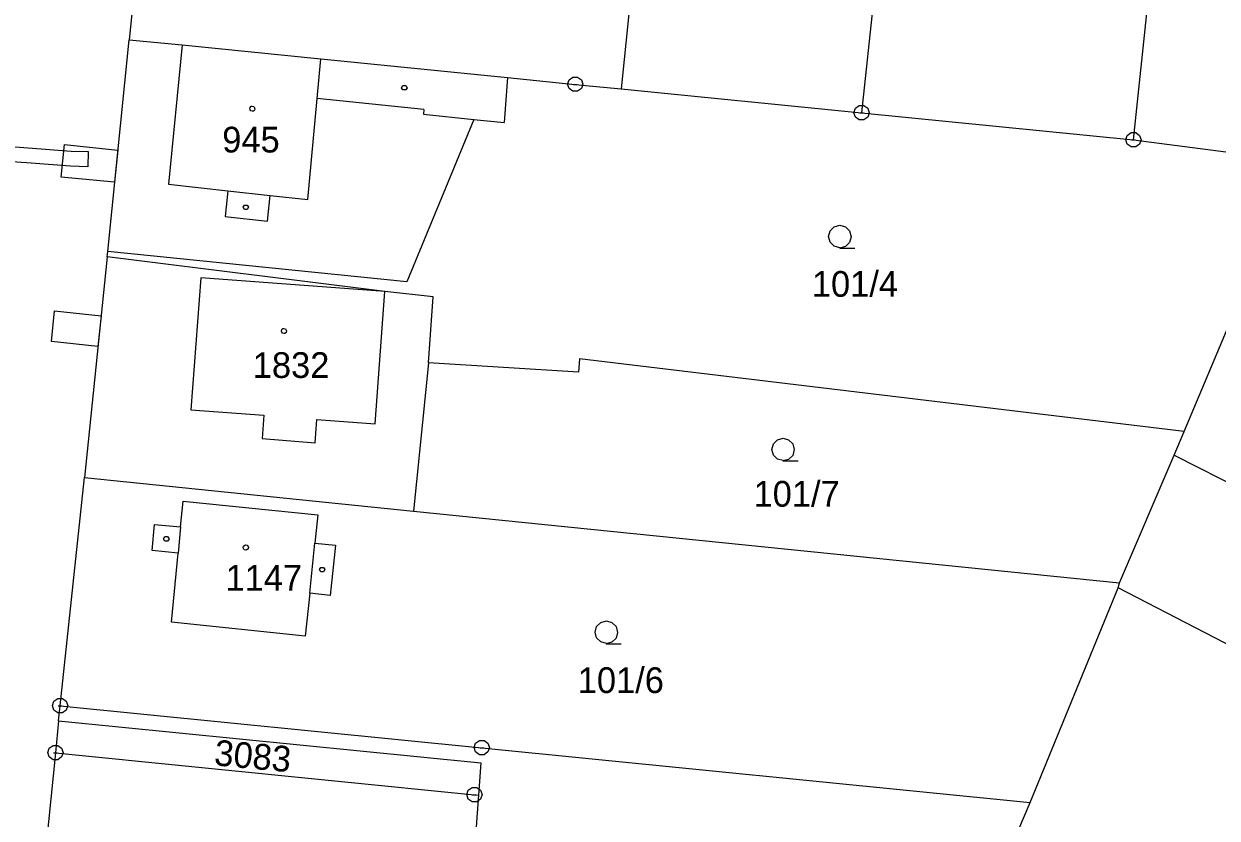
# Model space of a CAD drawing. Extents: x -777309 to -774195, y -1144706 to -1143600.
# Drawn here: x -775173 to -775094.2, y -1144329.3 to -1144276.8 of the extents above; entities that cross this region are included whole.
import ezdxf

# ---------------------------------------------------------------- set-up
doc = ezdxf.new("R2010")
doc.units = 0
for name, color, linetype in [('1', 7, 'Continuous'), ('12', 7, 'Continuous'), ('13', 7, 'Continuous'), ('2', 7, 'Continuous'), ('3', 7, 'Continuous'), ('4', 7, 'Continuous'), ('5', 7, 'Continuous'), ('8', 7, 'Continuous')]:
    doc.layers.add(name, color=color, linetype=linetype)

msp = doc.modelspace()

# ---------------------------------------------------------------- linework, layer by layer
at = {"layer": '1'}
for p, q in [((-775099.74, -1144284.49), (-775096.95, -1144258.04)), ((-775164.29, -1144260.43), (-775166.06, -1144277.88)), ((-775131.75, -1144263.67), (-775133.58, -1144281.12)), ((-775115.73, -1144264.21), (-775117.69, -1144282.7)), ((-775167.48, -1144291.85), (-775166.06, -1144277.88)), ((-775166.06, -1144277.88), (-775162.55, -1144278.22)), ((-775162.55, -1144278.22), (-775153.4, -1144279.14)), ((-775153.4, -1144279.14), (-775141.07, -1144280.37)), ((-775141.07, -1144280.37), (-775141.3, -1144283.35)), ((-775141.07, -1144280.37), (-775136.6, -1144280.82)), ((-775136.6, -1144280.82), (-775133.58, -1144281.12)), ((-775133.58, -1144281.12), (-775117.69, -1144282.7)), ((-775117.69, -1144282.7), (-775099.74, -1144284.49)), ((-775143.29, -1144283.14), (-775147.73, -1144293.87)), ((-775143.29, -1144283.14), (-775141.3, -1144283.35)), ((-775099.74, -1144284.49), (-775089.18, -1144285.87)), ((-775167.52, -1144292.21), (-775169, -1144306.79)), ((-775167.52, -1144292.21), (-775167.48, -1144291.85)), ((-775149.18, -1144294.5), (-775167.52, -1144292.21)), ((-775147.73, -1144293.87), (-775167.48, -1144291.85)), ((-775145.99, -1144294.86), (-775149.18, -1144294.5)), ((-775146.29, -1144299.21), (-775145.99, -1144294.86)), ((-775096.39, -1144303.74), (-775093.25, -1144296.26)), ((-775146.29, -1144299.21), (-775147.28, -1144309)), ((-775136.38, -1144299.82), (-775146.29, -1144299.21)), ((-775136.33, -1144298.95), (-775136.38, -1144299.82)), ((-775096.39, -1144303.74), (-775136.33, -1144298.95)), ((-775097.05, -1144305.31), (-775096.39, -1144303.74)), ((-775100.66, -1144313.73), (-775097.05, -1144305.31)), ((-775097.05, -1144305.31), (-775056.83, -1144325.83)), ((-775170.62, -1144321.86), (-775169, -1144306.79)), ((-775169, -1144306.79), (-775147.28, -1144309)), ((-775162.67, -1144310.05), (-775162.5, -1144308.34)), ((-775162.5, -1144308.34), (-775153.6, -1144309.26)), ((-775147.28, -1144309), (-775100.66, -1144313.73)), ((-775164.55, -1144311.61), (-775164.38, -1144309.89)), ((-775164.38, -1144309.89), (-775162.67, -1144310.05)), ((-775153.6, -1144309.26), (-775153.79, -1144311.12)), ((-775153.79, -1144311.12), (-775152.43, -1144311.26)), ((-775152.43, -1144311.26), (-775152.78, -1144314.57)), ((-775162.83, -1144311.77), (-775164.55, -1144311.61)), ((-775163.26, -1144316.34), (-775162.83, -1144311.77)), ((-775100.74, -1144314.07), (-775100.66, -1144313.73)), ((-775154.13, -1144314.43), (-775154.43, -1144317.26)), ((-775152.78, -1144314.57), (-775154.13, -1144314.43)), ((-775106.56, -1144328.24), (-775100.74, -1144314.07)), ((-775062.91, -1144333.66), (-775100.74, -1144314.07)), ((-775154.43, -1144317.26), (-775163.26, -1144316.34)), ((-775170.72, -1144322.85), (-775170.62, -1144321.86)), ((-775170.62, -1144321.86), (-775142.77, -1144324.63)), ((-775170.72, -1144322.85), (-775170.93, -1144324.96)), ((-775170.72, -1144322.85), (-775142.83, -1144325.63)), ((-775142.77, -1144324.63), (-775106.56, -1144328.24)), ((-775170.93, -1144324.96), (-775172.87, -1144344.25)), ((-775170.93, -1144324.96), (-775143.26, -1144327.74)), ((-775142.83, -1144325.63), (-775142.99, -1144327.77)), ((-775142.99, -1144327.77), (-775144.74, -1144351.18)), ((-775143.26, -1144327.74), (-775142.99, -1144327.77)), ((-775108.85, -1144333.58), (-775106.56, -1144328.24))]:
    msp.add_line(p, q, dxfattribs=at)
at = {"layer": '12'}
for p, q in [((-775162.55, -1144278.22), (-775163.46, -1144287.42)), ((-775162.55, -1144278.22), (-775153.4, -1144279.14)), ((-775153.64, -1144281.75), (-775153.4, -1144279.14)), ((-775154.27, -1144288.43), (-775153.64, -1144281.75)), ((-775163.46, -1144287.42), (-775159.54, -1144287.85)), ((-775159.54, -1144287.85), (-775156.75, -1144288.16)), ((-775156.75, -1144288.16), (-775154.27, -1144288.43)), ((-775161.33, -1144293.6), (-775161.98, -1144302.32)), ((-775149.18, -1144294.5), (-775161.33, -1144293.6)), ((-775149.82, -1144303.23), (-775149.18, -1144294.5)), ((-775161.98, -1144302.32), (-775157.17, -1144302.67)), ((-775157.17, -1144302.67), (-775157.28, -1144304.21)), ((-775153.78, -1144304.49), (-775153.67, -1144302.95)), ((-775153.67, -1144302.95), (-775149.82, -1144303.23)), ((-775157.28, -1144304.21), (-775153.78, -1144304.49)), ((-775162.67, -1144310.05), (-775162.5, -1144308.34)), ((-775162.5, -1144308.34), (-775153.6, -1144309.26)), ((-775153.6, -1144309.26), (-775153.79, -1144311.12)), ((-775162.67, -1144310.05), (-775162.83, -1144311.77)), ((-775154.13, -1144314.43), (-775153.79, -1144311.12)), ((-775163.26, -1144316.34), (-775162.83, -1144311.77)), ((-775154.13, -1144314.43), (-775154.43, -1144317.26)), ((-775154.43, -1144317.26), (-775163.26, -1144316.34))]:
    msp.add_line(p, q, dxfattribs=at)
at = {"layer": '13'}
for p, q in [((-775177.45, -1144284.68), (-775172.45, -1144285.03)), ((-775172.45, -1144285.03), (-775169.89, -1144285.23)), ((-775170.55, -1144286.94), (-775170.33, -1144284.8)), ((-775170.33, -1144284.8), (-775166.8, -1144285.16)), ((-775169.89, -1144285.23), (-775168.76, -1144285.26)), ((-775168.76, -1144285.26), (-775168.78, -1144286.26)), ((-775166.8, -1144285.16), (-775167.02, -1144287.29)), ((-775172.53, -1144286.03), (-775177.57, -1144285.68)), ((-775169.93, -1144286.23), (-775172.53, -1144286.03)), ((-775168.78, -1144286.26), (-775169.93, -1144286.23)), ((-775167.02, -1144287.29), (-775170.55, -1144286.94)), ((-775171.2, -1144297.81), (-775171, -1144295.78)), ((-775171, -1144295.78), (-775167.91, -1144296.1)), ((-775167.91, -1144296.1), (-775168.12, -1144298.13)), ((-775168.12, -1144298.13), (-775171.2, -1144297.81))]:
    msp.add_line(p, q, dxfattribs=at)
at = {"layer": '3'}
for points in [[(-775119.12, -1144291.61), (-775119.5, -1144291.51), (-775119.77, -1144291.24), (-775119.87, -1144290.87), (-775119.77, -1144290.5), (-775119.5, -1144290.23), (-775119.13, -1144290.13), (-775118.76, -1144290.23), (-775118.49, -1144290.5), (-775118.39, -1144290.88), (-775118.49, -1144291.26), (-775118.76, -1144291.53), (-775119.14, -1144291.63), (-775118.14, -1144291.63)], [(-775122.87, -1144305.67), (-775123.25, -1144305.57), (-775123.52, -1144305.3), (-775123.62, -1144304.93), (-775123.52, -1144304.56), (-775123.25, -1144304.29), (-775122.88, -1144304.19), (-775122.51, -1144304.29), (-775122.24, -1144304.56), (-775122.14, -1144304.94), (-775122.24, -1144305.32), (-775122.51, -1144305.59), (-775122.89, -1144305.69), (-775121.89, -1144305.69)], [(-775134.54, -1144317.74), (-775134.92, -1144317.64), (-775135.19, -1144317.37), (-775135.29, -1144317), (-775135.19, -1144316.63), (-775134.92, -1144316.36), (-775134.55, -1144316.26), (-775134.18, -1144316.36), (-775133.91, -1144316.63), (-775133.81, -1144317.01), (-775133.91, -1144317.39), (-775134.18, -1144317.66), (-775134.56, -1144317.76), (-775133.56, -1144317.76)]]:
    msp.add_lwpolyline(points, dxfattribs=at)
at = {"layer": '4'}
for p, q in [((-775162.55, -1144278.22), (-775163.46, -1144287.42)), ((-775153.64, -1144281.75), (-775153.4, -1144279.14)), ((-775154.27, -1144288.43), (-775153.64, -1144281.75)), ((-775146.6, -1144282.49), (-775153.64, -1144281.75)), ((-775146.6, -1144282.49), (-775146.63, -1144282.79)), ((-775146.63, -1144282.79), (-775143.29, -1144283.14)), ((-775163.46, -1144287.42), (-775159.54, -1144287.85)), ((-775159.54, -1144287.85), (-775159.73, -1144289.55)), ((-775159.54, -1144287.85), (-775156.75, -1144288.16)), ((-775156.93, -1144289.86), (-775156.75, -1144288.16)), ((-775156.75, -1144288.16), (-775154.27, -1144288.43)), ((-775159.73, -1144289.55), (-775156.93, -1144289.86)), ((-775161.33, -1144293.6), (-775161.98, -1144302.32)), ((-775149.18, -1144294.5), (-775161.33, -1144293.6)), ((-775149.82, -1144303.23), (-775149.18, -1144294.5)), ((-775161.98, -1144302.32), (-775157.17, -1144302.67)), ((-775157.17, -1144302.67), (-775157.28, -1144304.21)), ((-775153.78, -1144304.49), (-775153.67, -1144302.95)), ((-775153.67, -1144302.95), (-775149.82, -1144303.23)), ((-775157.28, -1144304.21), (-775153.78, -1144304.49)), ((-775162.67, -1144310.05), (-775162.83, -1144311.77)), ((-775154.13, -1144314.43), (-775153.79, -1144311.12))]:
    msp.add_line(p, q, dxfattribs=at)
at = {"layer": '5'}
for points in [[(-775147.8, -1144280.89), (-775147.71, -1144281.04), (-775147.8, -1144281.19), (-775147.98, -1144281.19), (-775148.07, -1144281.04), (-775147.98, -1144280.89)], [(-775157.93, -1144282.26), (-775157.83, -1144282.28), (-775157.78, -1144282.37), (-775157.76, -1144282.43), (-775157.78, -1144282.52), (-775157.86, -1144282.59), (-775157.93, -1144282.6), (-775158.02, -1144282.57), (-775158.08, -1144282.51), (-775158.1, -1144282.43), (-775158.08, -1144282.34), (-775158, -1144282.27)], [(-775158.27, -1144288.79), (-775158.18, -1144288.94), (-775158.27, -1144289.09), (-775158.45, -1144289.09), (-775158.54, -1144288.94), (-775158.45, -1144288.79)], [(-775155.84, -1144296.94), (-775155.74, -1144296.96), (-775155.69, -1144297.05), (-775155.67, -1144297.11), (-775155.69, -1144297.2), (-775155.77, -1144297.27), (-775155.84, -1144297.28), (-775155.93, -1144297.25), (-775155.99, -1144297.19), (-775156.01, -1144297.11), (-775155.99, -1144297.02), (-775155.91, -1144296.95)], [(-775163.52, -1144310.68), (-775163.43, -1144310.83), (-775163.52, -1144310.98), (-775163.7, -1144310.98), (-775163.79, -1144310.83), (-775163.7, -1144310.68)], [(-775158.36, -1144311.24), (-775158.26, -1144311.26), (-775158.21, -1144311.35), (-775158.19, -1144311.41), (-775158.21, -1144311.5), (-775158.29, -1144311.57), (-775158.36, -1144311.58), (-775158.45, -1144311.55), (-775158.51, -1144311.49), (-775158.53, -1144311.41), (-775158.51, -1144311.32), (-775158.43, -1144311.25)], [(-775153.22, -1144312.72), (-775153.13, -1144312.87), (-775153.22, -1144313.02), (-775153.4, -1144313.02), (-775153.49, -1144312.87), (-775153.4, -1144312.72)]]:
    msp.add_lwpolyline(points, close=True, dxfattribs=at)
at = {"layer": '8'}
for p, q in [((-775136.72, -1144280.82), (-775136.48, -1144280.82)), ((-775117.81, -1144282.7), (-775117.57, -1144282.7)), ((-775099.86, -1144284.49), (-775099.62, -1144284.49)), ((-775170.74, -1144321.86), (-775170.5, -1144321.86)), ((-775142.89, -1144324.63), (-775142.65, -1144324.63)), ((-775171.05, -1144324.96), (-775170.81, -1144324.96)), ((-775143.38, -1144327.74), (-775143.14, -1144327.74))]:
    msp.add_line(p, q, dxfattribs=at)
for points in [[(-775136.45, -1144280.34), (-775136.2, -1144280.52), (-775136.1, -1144280.81), (-775136.2, -1144281.1), (-775136.45, -1144281.28), (-775136.76, -1144281.28), (-775137.01, -1144281.1), (-775137.11, -1144280.81), (-775137.01, -1144280.52), (-775136.76, -1144280.34)], [(-775117.54, -1144282.22), (-775117.29, -1144282.4), (-775117.19, -1144282.69), (-775117.29, -1144282.98), (-775117.54, -1144283.16), (-775117.85, -1144283.16), (-775118.1, -1144282.98), (-775118.2, -1144282.69), (-775118.1, -1144282.4), (-775117.85, -1144282.22)], [(-775099.59, -1144284.01), (-775099.34, -1144284.19), (-775099.24, -1144284.48), (-775099.34, -1144284.77), (-775099.59, -1144284.95), (-775099.9, -1144284.95), (-775100.15, -1144284.77), (-775100.25, -1144284.48), (-775100.15, -1144284.19), (-775099.9, -1144284.01)], [(-775170.47, -1144321.38), (-775170.22, -1144321.56), (-775170.12, -1144321.85), (-775170.22, -1144322.14), (-775170.47, -1144322.32), (-775170.78, -1144322.32), (-775171.03, -1144322.14), (-775171.13, -1144321.85), (-775171.03, -1144321.56), (-775170.78, -1144321.38)], [(-775170.78, -1144324.48), (-775170.53, -1144324.66), (-775170.43, -1144324.95), (-775170.53, -1144325.24), (-775170.78, -1144325.42), (-775171.09, -1144325.42), (-775171.34, -1144325.24), (-775171.44, -1144324.95), (-775171.34, -1144324.66), (-775171.09, -1144324.48)], [(-775142.62, -1144324.15), (-775142.37, -1144324.33), (-775142.27, -1144324.62), (-775142.37, -1144324.91), (-775142.62, -1144325.09), (-775142.93, -1144325.09), (-775143.18, -1144324.91), (-775143.28, -1144324.62), (-775143.18, -1144324.33), (-775142.93, -1144324.15)], [(-775143.11, -1144327.26), (-775142.86, -1144327.44), (-775142.76, -1144327.73), (-775142.86, -1144328.02), (-775143.11, -1144328.2), (-775143.42, -1144328.2), (-775143.67, -1144328.02), (-775143.77, -1144327.73), (-775143.67, -1144327.44), (-775143.42, -1144327.26)]]:
    msp.add_lwpolyline(points, close=True, dxfattribs=at)

# ---------------------------------------------------------------- texts
at = {"layer": '2'}
for s, p in [('945', (-775159.913, -1144285.32)), ('101/4', (-775120.977, -1144294.85)), ('1832', (-775157.897, -1144300.21)), ('101/7', (-775124.827, -1144308.71)), ('1147', (-775159.697, -1144314.26)), ('101/6', (-775136.437, -1144321.02))]:
    msp.add_text(s, height=1.7, dxfattribs=at).set_placement(p)
msp.add_text('3083', height=1.7, rotation=354.71817, dxfattribs=at).set_placement((-775160.489, -1144325.786))

doc.saveas('drawing.dxf')
